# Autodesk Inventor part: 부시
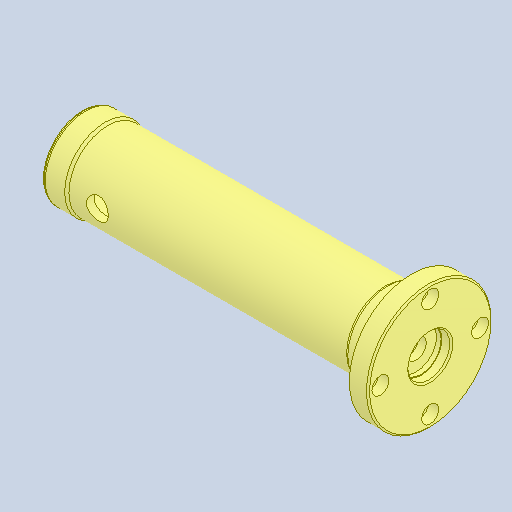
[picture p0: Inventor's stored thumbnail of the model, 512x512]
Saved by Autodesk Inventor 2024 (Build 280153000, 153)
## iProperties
Created: 2024-08
Part Number: 부시
Material: 강철, 탄소
Document SubType Name: Modeling
Designer: user
Density: 7.85 g/cm^3
Appearance: 기본값
Author: jhkim
Sending System: Autodesk Inventor 2025
Preprocessor: ST-DEVELOPER v20
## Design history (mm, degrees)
feature "솔리드1"
node "솔리드2"
